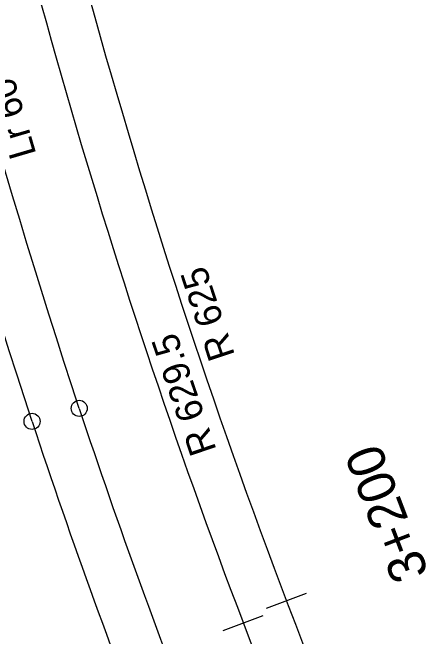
# Model space of a CAD drawing. Extents: x 149855 to 151460, y 6580726 to 6583068.
# Drawn here: x 151025.2 to 151063.9, y 6581493.4 to 6581551.6 of the extents above; entities that cross this region are included whole.
import ezdxf

# ---------------------------------------------------------------- set-up
doc = ezdxf.new("R2010")
doc.units = 0
for name, color, linetype in [('Hektometer L', 7, 'Continuous'), ('Hektometer T', 7, 'Continuous'), ('Spårgeometri T', 7, 'Continuous'), ('Spårmitt L', 7, 'Continuous'), ('Tp bef behålls P', 7, 'Continuous')]:
    doc.layers.add(name, color=color, linetype=linetype)

msp = doc.modelspace()

# ---------------------------------------------------------------- linework, layer by layer
at = {"layer": 'Hektometer L'}
for points in [[(151048.925, 6581496.027), (151052.664, 6581497.448)], [(151044.904, 6581493.94), (151048.642, 6581495.364)]]:
    msp.add_lwpolyline(points, dxfattribs=at)
at = {"layer": 'Spårmitt L'}
for points in [[(151027.055, 6581513.464), (151026.336, 6581515.657), (151025.624, 6581517.852), (151024.92, 6581520.05), (151024.224, 6581522.25), (151023.534, 6581524.452), (151022.852, 6581526.657), (151022.176, 6581528.863), (151021.506, 6581531.071), (151020.843, 6581533.282), (151020.184, 6581535.493), (151019.531, 6581537.707), (151018.883, 6581539.922), (151018.24, 6581542.138), (151017.601, 6581544.355), (151016.965, 6581546.574), (151016.334, 6581548.793), (151015.705, 6581551.014), (151015.08, 6581553.235)], [(151031.461, 6581514.676), (151030.74, 6581516.868), (151030.028, 6581519.063), (151029.323, 6581521.261), (151028.626, 6581523.461), (151027.936, 6581525.663), (151027.253, 6581527.867), (151026.576, 6581530.073), (151025.906, 6581532.282), (151025.242, 6581534.492), (151024.583, 6581536.703), (151023.93, 6581538.917), (151023.281, 6581541.131), (151022.637, 6581543.347), (151021.998, 6581545.565), (151021.362, 6581547.783), (151020.73, 6581550.003), (151020.102, 6581552.223)]]:
    msp.add_lwpolyline(points, dxfattribs=at)
for centre, radius, start, end in [((151635.021, 6581718.782), 625, 192.820008, 203.761052), ((151635.017, 6581718.794), 629.5, 193.95613, 203.78913), ((151596.816, 6581701.742), 595.5, 198.30841, 205.00011), ((151596.765, 6581701.695), 600, 198.28341, 205.052007), ((154379.055, 6582805.47), 3603.5, 201.252844, 202.283548)]:
    msp.add_arc(centre, radius, start, end, dxfattribs=at)
at = {"layer": 'Tp bef behålls P'}
for centre in [(151031.461, 6581514.676), (151027.055, 6581513.464)]:
    msp.add_circle(centre, 0.75, dxfattribs=at)

# ---------------------------------------------------------------- texts
at = {"layer": 'Hektometer T'}
msp.add_text('3+200', height=3.5, rotation=110.80879, dxfattribs=at).set_placement((151064.117, 6581499.297))
at = {"layer": 'Spårgeometri T'}
for s, rotation, p in [('Lr 60', 106.3841, (151027.471, 6581538.403)), ('R 625', 108.29073, (151046.015, 6581519.631)), ('R 629.5', 108.87263, (151044.287, 6581510.803))]:
    msp.add_text(s, height=2.5, rotation=rotation, dxfattribs=at).set_placement(p)

doc.saveas('drawing.dxf')
